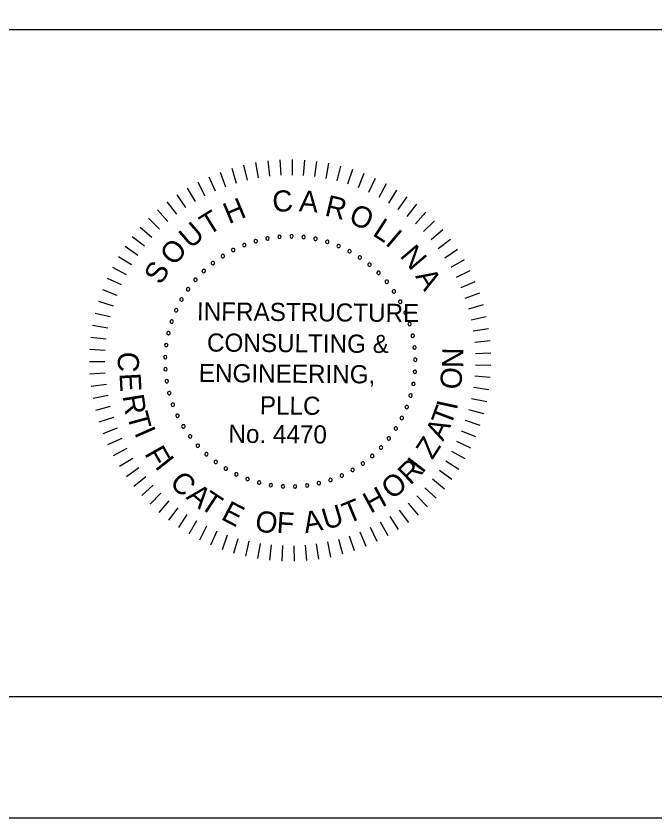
# Model space of a CAD drawing. Extents: x -125.5 to -89.4, y -5.1 to 16.9.
# Drawn here: x -100.331 to -97.696, y -5.066 to -1.761 of the extents above; entities that cross this region are included whole.
import ezdxf

# ---------------------------------------------------------------- set-up
doc = ezdxf.new("R2010")
doc.units = 0
for name, color, linetype in [('BR_BORDER LINES', 7, 'Continuous'), ('BR_TEXT', 7, 'Continuous'), ('Level 31', 7, 'Continuous')]:
    doc.layers.add(name, color=color, linetype=linetype)

msp = doc.modelspace()

# ---------------------------------------------------------------- linework, layer by layer
at = {"layer": 'BR_BORDER LINES'}
for p, q in [((-102.8989, -1.8161), (-97.5337, -1.8161)), ((-123.6994, -4.5662), (-90.0334, -4.5662))]:
    msp.add_line(p, q, dxfattribs=at)
at = {"layer": 'BR_TEXT'}
for p, q in [((-99.3925, -2.3754), (-99.3776, -2.4373)), ((-99.343, -2.3651), (-99.332, -2.4278)), ((-99.2931, -2.3579), (-99.2858, -2.4212)), ((-99.2427, -2.3538), (-99.2394, -2.4174)), ((-99.1923, -2.3527), (-99.1928, -2.4164)), ((-99.1418, -2.3548), (-99.1462, -2.4183)), ((-99.0916, -2.3599), (-99.0999, -2.423)), ((-99.0418, -2.368), (-99.0539, -2.4305)), ((-98.9925, -2.3792), (-99.0084, -2.4408)), ((-99.489, -2.4048), (-99.4667, -2.4644)), ((-99.4412, -2.3886), (-99.4226, -2.4495)), ((-98.9441, -2.3933), (-98.9637, -2.4539)), ((-98.8966, -2.4104), (-98.9199, -2.4696)), ((-99.5813, -2.4457), (-99.5519, -2.5022)), ((-99.5358, -2.4238), (-99.5099, -2.482)), ((-98.8502, -2.4303), (-98.877, -2.488)), ((-99.6253, -2.4703), (-99.5926, -2.5249)), ((-98.8051, -2.453), (-98.8354, -2.509)), ((-98.7615, -2.4785), (-98.7952, -2.5325)), ((-99.6678, -2.4975), (-99.6318, -2.55)), ((-98.7195, -2.5065), (-98.7564, -2.5584)), ((-99.7086, -2.5273), (-99.6694, -2.5775)), ((-98.6793, -2.5371), (-98.7193, -2.5866)), ((-99.7475, -2.5595), (-99.7053, -2.6072)), ((-98.6411, -2.57), (-98.684, -2.617)), ((-99.7843, -2.5941), (-99.7393, -2.6391)), ((-98.6049, -2.6052), (-98.6506, -2.6495)), ((-99.819, -2.6308), (-99.7713, -2.673)), ((-98.571, -2.6426), (-98.6193, -2.684)), ((-99.8513, -2.6695), (-99.8012, -2.7087)), ((-98.5393, -2.6819), (-98.5901, -2.7204)), ((-99.8813, -2.7102), (-99.8288, -2.7463)), ((-98.5102, -2.7232), (-98.5632, -2.7584)), ((-99.9087, -2.7526), (-99.8541, -2.7854)), ((-98.4836, -2.7661), (-98.5387, -2.798)), ((-99.9334, -2.7965), (-99.877, -2.826)), ((-99.9555, -2.842), (-99.8973, -2.8679)), ((-98.4597, -2.8105), (-98.5166, -2.839)), ((-98.4385, -2.8563), (-98.497, -2.8813)), ((-99.9747, -2.8886), (-99.9151, -2.911)), ((-98.4202, -2.9034), (-98.4801, -2.9248)), ((-99.991, -2.9364), (-99.9302, -2.9551)), ((-98.4047, -2.9514), (-98.4659, -2.9691)), ((-100.0044, -2.9851), (-99.9426, -3)), ((-98.3922, -3.0004), (-98.4544, -3.0143)), ((-100.0149, -3.0345), (-99.9522, -3.0456)), ((-98.3828, -3.05), (-98.4456, -3.0601)), ((-100.0222, -3.0844), (-99.959, -3.0917)), ((-98.3763, -3.1), (-98.4397, -3.1063)), ((-100.0266, -3.1347), (-99.963, -3.1382)), ((-98.373, -3.1504), (-98.4366, -3.1528)), ((-100.0278, -3.1852), (-99.9641, -3.1847)), ((-98.3727, -3.2009), (-98.4363, -3.1994)), ((-100.026, -3.2356), (-99.9625, -3.2313)), ((-98.3755, -3.2513), (-98.4389, -3.2459)), ((-100.0211, -3.2859), (-99.9579, -3.2777)), ((-98.3813, -3.3014), (-98.4443, -3.2922)), ((-100.0131, -3.3357), (-99.9506, -3.3237)), ((-98.3902, -3.3511), (-98.4525, -3.3381)), ((-100.0021, -3.385), (-99.9405, -3.3692)), ((-98.4021, -3.4002), (-98.4635, -3.3834)), ((-99.9882, -3.4335), (-99.9276, -3.414)), ((-98.417, -3.4484), (-98.4773, -3.4279)), ((-99.9713, -3.4811), (-99.912, -3.4579)), ((-99.9515, -3.5276), (-99.8937, -3.5008)), ((-98.4348, -3.4957), (-98.4937, -3.4715)), ((-98.4554, -3.5417), (-98.5128, -3.514)), ((-99.929, -3.5727), (-99.8729, -3.5425)), ((-98.4789, -3.5865), (-98.5344, -3.5553)), ((-99.9037, -3.6164), (-99.8496, -3.5828)), ((-98.505, -3.6297), (-98.5585, -3.5952)), ((-99.8758, -3.6585), (-99.8239, -3.6217)), ((-98.5336, -3.6712), (-98.5849, -3.6335)), ((-99.8454, -3.6988), (-99.7958, -3.6589)), ((-99.8126, -3.7372), (-99.7655, -3.6943)), ((-98.5648, -3.7109), (-98.6137, -3.6702)), ((-99.7775, -3.7735), (-99.7331, -3.7278)), ((-98.5983, -3.7487), (-98.6447, -3.705)), ((-99.7403, -3.8076), (-99.6988, -3.7593)), ((-98.6341, -3.7843), (-98.6777, -3.7379)), ((-99.701, -3.8393), (-99.6626, -3.7886)), ((-98.7118, -3.8487), (-98.7494, -3.7974)), ((-98.672, -3.8177), (-98.7126, -3.7687)), ((-99.6599, -3.8687), (-99.6246, -3.8157)), ((-98.7534, -3.8772), (-98.7879, -3.8237)), ((-99.6171, -3.8954), (-99.5851, -3.8404)), ((-99.5728, -3.9195), (-99.5442, -3.8626)), ((-98.7967, -3.9032), (-98.8278, -3.8476)), ((-99.527, -3.9408), (-99.5019, -3.8823)), ((-99.48, -3.9594), (-99.4586, -3.8994)), ((-98.8877, -3.9469), (-98.9118, -3.888)), ((-98.8416, -3.9264), (-98.8692, -3.8691)), ((-99.432, -3.975), (-99.4143, -3.9138)), ((-99.3832, -3.9876), (-99.3692, -3.9255)), ((-99.0324, -3.991), (-99.0454, -3.9286)), ((-98.9833, -3.9792), (-99.0001, -3.9178)), ((-98.935, -3.9645), (-98.9555, -3.9042)), ((-99.3336, -3.9973), (-99.3234, -3.9344)), ((-99.2836, -4.0039), (-99.2772, -3.9406)), ((-99.2332, -4.0075), (-99.2307, -3.9438)), ((-99.1827, -4.0079), (-99.1841, -3.9443)), ((-99.1323, -4.0053), (-99.1376, -3.9419)), ((-99.0821, -3.9997), (-99.0913, -3.9367))]:
    msp.add_line(p, q, dxfattribs=at)
for centre, start, end in [((-99.2939, -2.6775), 10.6038, 190.6038), ((-99.2939, -2.6775), 190.6038, 10.6038), ((-99.2445, -2.6708), 5.0653, 185.0653), ((-99.2445, -2.6708), 185.0653, 5.0653), ((-99.1947, -2.6689), 359.5268, 179.5268), ((-99.1947, -2.6689), 179.5268, 359.5268), ((-99.145, -2.6718), 173.9884, 353.9884), ((-99.145, -2.6718), 353.9884, 173.9884), ((-99.0957, -2.6795), 348.4499, 168.4499), ((-99.3896, -2.705), 21.6807, 201.6807), ((-99.3896, -2.705), 201.6807, 21.6807), ((-99.3424, -2.6889), 16.1422, 196.1422), ((-99.3424, -2.6889), 196.1422, 16.1422), ((-99.0957, -2.6795), 168.4499, 348.4499), ((-99.0475, -2.6919), 162.9114, 342.9114), ((-99.0475, -2.6919), 342.9114, 162.9114), ((-99.0006, -2.709), 157.373, 337.373), ((-99.0006, -2.709), 337.373, 157.373), ((-99.435, -2.7255), 27.2191, 207.2191), ((-99.435, -2.7255), 207.2191, 27.2191), ((-98.9557, -2.7304), 151.8345, 331.8345), ((-98.9557, -2.7304), 331.8345, 151.8345), ((-99.5188, -2.7792), 38.2961, 218.2961), ((-99.5188, -2.7792), 218.2961, 38.2961), ((-99.4782, -2.7503), 32.7576, 212.7576), ((-99.4782, -2.7503), 212.7576, 32.7576), ((-98.913, -2.7561), 146.2961, 326.2961), ((-98.913, -2.7561), 326.2961, 146.2961), ((-99.5564, -2.8119), 43.8345, 223.8345), ((-99.5564, -2.8119), 223.8345, 43.8345), ((-98.873, -2.7858), 140.7576, 320.7576), ((-98.873, -2.7858), 320.7576, 140.7576), ((-99.5907, -2.848), 49.373, 229.373), ((-98.836, -2.8192), 135.2191, 315.2191), ((-98.836, -2.8192), 315.2191, 135.2191), ((-99.5907, -2.848), 229.373, 49.373), ((-98.8024, -2.8561), 129.6807, 309.6807), ((-98.8024, -2.8561), 309.6807, 129.6807), ((-99.6214, -2.8873), 54.9114, 234.9114), ((-99.6214, -2.8873), 234.9114, 54.9114), ((-98.7726, -2.896), 124.1422, 304.1422), ((-98.7726, -2.896), 304.1422, 124.1422), ((-99.6481, -2.9293), 60.4499, 240.4499), ((-99.6481, -2.9293), 240.4499, 60.4499), ((-98.7467, -2.9386), 118.6038, 298.6038), ((-98.7467, -2.9386), 298.6038, 118.6038), ((-99.6706, -2.9738), 65.9884, 245.9884), ((-99.6706, -2.9738), 245.9884, 65.9884), ((-98.7251, -2.9835), 113.0653, 293.0653), ((-98.7251, -2.9835), 293.0653, 113.0653), ((-99.6888, -3.0202), 71.5268, 251.5268), ((-99.6888, -3.0202), 251.5268, 71.5268), ((-98.7079, -3.0302), 107.5268, 287.5268), ((-98.7079, -3.0302), 287.5268, 107.5268), ((-99.7024, -3.0681), 77.0653, 257.0653), ((-99.7024, -3.0681), 257.0653, 77.0653), ((-98.6953, -3.0785), 101.9884, 281.9884), ((-98.6953, -3.0785), 281.9884, 101.9884), ((-99.7113, -3.1172), 82.6038, 262.6038), ((-99.7113, -3.1172), 262.6038, 82.6038), ((-98.6874, -3.1277), 96.4499, 276.4499), ((-98.6874, -3.1277), 276.4499, 96.4499), ((-99.7154, -3.1668), 88.1422, 268.1422), ((-99.7154, -3.1668), 268.1422, 88.1422), ((-98.6843, -3.1774), 90.9114, 270.9114), ((-98.6843, -3.1774), 270.9114, 90.9114), ((-99.7147, -3.2167), 93.6807, 273.6807), ((-99.7147, -3.2167), 273.6807, 93.6807), ((-98.686, -3.2272), 85.373, 265.373), ((-98.686, -3.2272), 265.373, 85.373), ((-99.7092, -3.2662), 99.2191, 279.2191), ((-99.7092, -3.2662), 279.2191, 99.2191), ((-98.6926, -3.2766), 79.8345, 259.8345), ((-98.6926, -3.2766), 259.8345, 79.8345), ((-99.6989, -3.3149), 104.7576, 284.7576), ((-99.6989, -3.3149), 284.7576, 104.7576), ((-98.7038, -3.3251), 74.2961, 254.2961), ((-98.7038, -3.3251), 254.2961, 74.2961), ((-99.684, -3.3625), 110.2961, 290.2961), ((-99.684, -3.3625), 290.2961, 110.2961), ((-98.7197, -3.3724), 68.7576, 248.7576), ((-98.7197, -3.3724), 248.7576, 68.7576), ((-99.6646, -3.4084), 115.8345, 295.8345), ((-99.6646, -3.4084), 295.8345, 115.8345), ((-98.7401, -3.4178), 63.2191, 243.2191), ((-98.7401, -3.4178), 243.2191, 63.2191), ((-99.6408, -3.4522), 121.373, 301.373), ((-99.6408, -3.4522), 301.373, 121.373), ((-98.7647, -3.4611), 57.6807, 237.6807), ((-98.7647, -3.4611), 237.6807, 57.6807), ((-99.6129, -3.4935), 126.9114, 306.9114), ((-99.6129, -3.4935), 306.9114, 126.9114), ((-98.7934, -3.5019), 52.1422, 232.1422), ((-98.7934, -3.5019), 232.1422, 52.1422), ((-99.5812, -3.5319), 132.4499, 312.4499), ((-99.5812, -3.5319), 312.4499, 132.4499), ((-98.826, -3.5396), 46.6038, 226.6038), ((-98.826, -3.5396), 226.6038, 46.6038), ((-99.5459, -3.5671), 137.9884, 317.9884), ((-99.5459, -3.5671), 317.9884, 137.9884), ((-98.862, -3.5741), 41.0653, 221.0653), ((-99.5074, -3.5987), 143.5268, 323.5268), ((-99.5074, -3.5987), 323.5268, 143.5268), ((-98.9012, -3.6049), 35.5268, 215.5268), ((-98.9012, -3.6049), 215.5268, 35.5268), ((-98.862, -3.5741), 221.0653, 41.0653), ((-99.466, -3.6264), 149.0653, 329.0653), ((-99.466, -3.6264), 329.0653, 149.0653), ((-98.9431, -3.6317), 29.9884, 209.9884), ((-98.9431, -3.6317), 209.9884, 29.9884), ((-99.4221, -3.65), 154.6038, 334.6038), ((-99.4221, -3.65), 334.6038, 154.6038), ((-99.3761, -3.6693), 160.1422, 340.1422), ((-99.3761, -3.6693), 340.1422, 160.1422), ((-99.0338, -3.6728), 18.9114, 198.9114), ((-98.9875, -3.6545), 24.4499, 204.4499), ((-98.9875, -3.6545), 204.4499, 24.4499), ((-99.3285, -3.684), 165.6807, 345.6807), ((-99.3285, -3.684), 345.6807, 165.6807), ((-99.2797, -3.6941), 351.2191, 171.2191), ((-99.2797, -3.6941), 171.2191, 351.2191), ((-99.2302, -3.6994), 356.7576, 176.7576), ((-99.2302, -3.6994), 176.7576, 356.7576), ((-99.1803, -3.6999), 2.2961, 182.2961), ((-99.1803, -3.6999), 182.2961, 2.2961), ((-99.1307, -3.6956), 7.8345, 187.8345), ((-99.1307, -3.6956), 187.8345, 7.8345), ((-99.0817, -3.6865), 13.373, 193.373), ((-99.0817, -3.6865), 193.373, 13.373), ((-99.0338, -3.6728), 198.9114, 18.9114)]:
    msp.add_arc(centre, 0.00701, start, end, dxfattribs=at)
at = {"layer": 'Level 31'}
msp.add_lwpolyline([(-125.5328, 16.9339), (-125.5328, -5.0661), (-89.5328, -5.0661), (-89.5328, 16.9339)], dxfattribs=at)

# ---------------------------------------------------------------- texts
at = {"layer": 'BR_TEXT'}
for s, height, rotation, p in [('C', 0.0872, 4.7281, (-99.2702, -2.5703)), ('H', 0.0872, 22.7882, (-99.453, -2.6197)), ('A', 0.0872, 355.6981, (-99.1657, -2.5654)), ('R', 0.0872, 346.6681, (-99.0615, -2.5824)), ('O', 0.0872, 337.638, (-98.9637, -2.6122)), ('T', 0.0872, 31.8182, (-99.5379, -2.6674)), ('U', 0.0872, 40.8482, (-99.6112, -2.7235)), ('L', 0.0872, 327.108, (-98.8649, -2.6626)), ('I', 0.0872, 319.578, (-98.8123, -2.7005)), ('O', 0.0872, 49.8782, (-99.6782, -2.7945)), ('N', 0.0872, 310.548, (-98.7515, -2.7512)), ('S', 0.0872, 58.9083, (-99.7336, -2.8727)), ('A', 0.0872, 301.5179, (-98.6864, -2.8336)), ('INFRASTRUCTURE', 0.074771, 359.5268, (-99.585, -3.0152)), ('CONSULTING &', 0.074771, 359.5268, (-99.5437, -3.1438)), ('N', 0.0872, 89.2085, (-98.4872, -3.2124)), ('C', 0.0872, 267.025, (-99.9086, -3.1426)), ('ENGINEERING,', 0.074771, 359.5268, (-99.5773, -3.2693)), ('O', 0.0872, 83.2085, (-98.4982, -3.3038)), ('E', 0.0872, 273.025, (-99.9042, -3.2342)), ('R', 0.0872, 279.025, (-99.8914, -3.3265)), ('PLLC', 0.07477, 359.5268, (-99.3256, -3.4028)), ('T', 0.0872, 69.3954, (-98.5394, -3.4556)), ('I', 0.0872, 77.9093, (-98.5137, -3.3881)), ('T', 0.0872, 285.025, (-99.874, -3.4053)), ('A', 0.0872, 63.3954, (-98.5702, -3.516)), ('I', 0.0872, 293.7713, (-99.8443, -3.4784)), ('No. 4470', 0.07477, 359.5268, (-99.4551, -3.5197)), ('Z', 0.0872, 57.3954, (-98.6141, -3.5923)), ('F', 0.0872, 299.7713, (-99.8031, -3.5644)), ('I', 0.0872, 308.5268, (-99.761, -3.6183)), ('R', 0.0872, 44.5268, (-98.7045, -3.6973)), ('I', 0.0872, 52.3339, (-98.6551, -3.65)), ('C', 0.0872, 314.5268, (-99.7017, -3.6884)), ('O', 0.0872, 38.5268, (-98.7811, -3.7572)), ('A', 0.0872, 320.5268, (-99.6325, -3.747)), ('H', 0.0872, 28.5268, (-98.8692, -3.8132)), ('T', 0.0872, 326.5268, (-99.5781, -3.7855)), ('E', 0.0872, 332.5268, (-99.4895, -3.8332)), ('T', 0.0872, 22.5268, (-98.9624, -3.855)), ('O', 0.0872, 350.5268, (-99.3494, -3.8821)), ('A', 0.0872, 10.5268, (-99.138, -3.8929)), ('U', 0.0872, 16.5268, (-99.0541, -3.8794)), ('F', 0.0872, 356.5268, (-99.2579, -3.8912))]:
    msp.add_text(s, height=height, rotation=rotation, dxfattribs=at).set_placement(p)

doc.saveas('drawing.dxf')
